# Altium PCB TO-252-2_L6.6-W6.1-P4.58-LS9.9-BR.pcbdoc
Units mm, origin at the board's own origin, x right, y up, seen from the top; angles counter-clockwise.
Board outline 23.61 x 19.41 mm, 2 copper layers (Top Layer, Bottom Layer), stack 0 mm thick; 1 components, 0 nets, 3 pads, 0 vias.
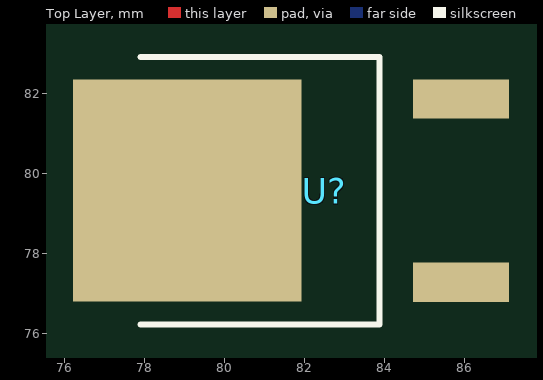
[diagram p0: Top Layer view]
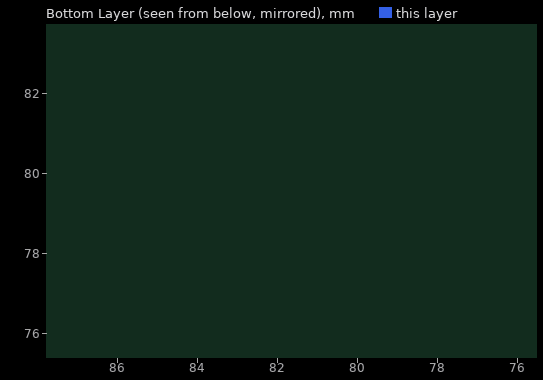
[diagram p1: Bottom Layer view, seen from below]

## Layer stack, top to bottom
Top Layer: signal copper (thickness not stored)
Bottom Layer: signal copper (thickness not stored)

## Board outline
93.457,69.85 69.85,69.85 69.85,89.256 93.457,89.256

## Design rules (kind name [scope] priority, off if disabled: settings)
PasteMaskExpansion "Paste Mask Expansion" [All] p1: expansion=0
SolderMaskExpansion "Solder Mask Expansion" [IsVia] p1: expansion=-25.4 istentingtop=TRUE
SolderMaskExpansion "Solder Mask Expansion" [All] p2: expansion=0.051 istentingtop=FALSE

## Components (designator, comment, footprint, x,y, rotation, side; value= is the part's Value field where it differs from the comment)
U? "" TO-252-2_L6.6-W6.1-P4.58-LS9.9-BR 82.479,79.56 r0 top

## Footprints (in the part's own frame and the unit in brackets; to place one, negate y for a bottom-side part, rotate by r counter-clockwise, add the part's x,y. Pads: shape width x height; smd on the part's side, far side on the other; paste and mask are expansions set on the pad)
TO-252-2_L6.6-W6.1-P4.58-LS9.9-BR [mm]
  rect 2.409x0.979 smd: 1(3.424,-2.29) 3(3.423,2.29)
  rect 5.711x5.548 smd: 2(-3.424,0)
  silkscreen extent -4.58,-3.35 1.38,3.35

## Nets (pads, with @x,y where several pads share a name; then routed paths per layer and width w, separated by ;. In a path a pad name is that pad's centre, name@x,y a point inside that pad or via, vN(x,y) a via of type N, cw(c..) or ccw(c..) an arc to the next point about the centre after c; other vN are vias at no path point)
pads on no net: U?.1 U?.2 U?.3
